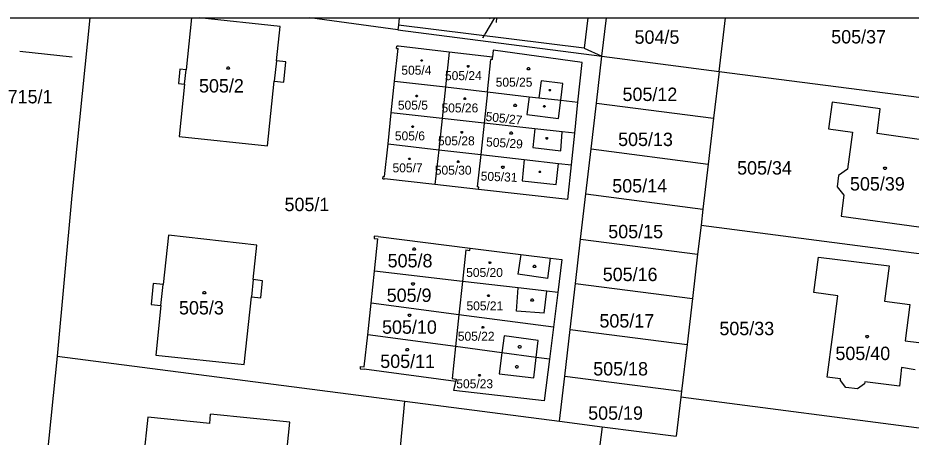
# Model space of a CAD drawing. Extents: x -639590 to -639298, y -1193269 to -1192863.
# Drawn here: x -639509.2 to -639395.8, y -1192916.5 to -1192863.3 of the extents above; entities that cross this region are included whole.
import ezdxf

# ---------------------------------------------------------------- set-up
doc = ezdxf.new("R2010")
doc.units = 0
for name, color, linetype in [('Vrstva 1', 7, 'Continuous'), ('Vrstva 2', 7, 'Continuous'), ('Vrstva 25', 7, 'Continuous'), ('Vrstva 4', 7, 'Continuous'), ('Vrstva 5', 7, 'Continuous'), ('Vrstva 61', 7, 'Continuous'), ('Vrstva 7', 7, 'Continuous')]:
    doc.layers.add(name, color=color, linetype=linetype)

msp = doc.modelspace()

# ---------------------------------------------------------------- linework, layer by layer
at = {"layer": 'Vrstva 1'}
for p, q in [((-639500.02, -1192863.27), (-639502.3, -1192885.82)), ((-639487.11, -1192863.27), (-639487.81, -1192869.85)), ((-639475.88, -1192864.37), (-639486.16, -1192863.27)), ((-639460.93, -1192864.78), (-639472.08, -1192863.27)), ((-639460.75, -1192863.27), (-639460.84, -1192864.19)), ((-639436.82, -1192863.27), (-639437.25, -1192867.1)), ((-639435.01, -1192868.14), (-639434.44, -1192863.27)), ((-639420.13, -1192870.07), (-639419.34, -1192863.27)), ((-639476.34, -1192868.73), (-639475.88, -1192864.37)), ((-639460.84, -1192864.19), (-639460.93, -1192864.78)), ((-639460.93, -1192864.78), (-639435.01, -1192868.14)), ((-639437.25, -1192867.1), (-639460.84, -1192864.19)), ((-639461.33, -1192871.31), (-639460.89, -1192867.17)), ((-639461.09, -1192867.15), (-639461.06, -1192866.85)), ((-639461.09, -1192867.15), (-639460.89, -1192867.17)), ((-639460.86, -1192866.87), (-639461.06, -1192866.85)), ((-639454.41, -1192867.62), (-639460.86, -1192866.87)), ((-639437.25, -1192867.1), (-639435.01, -1192868.14)), ((-639454.41, -1192867.62), (-639454.88, -1192872.05)), ((-639448.89, -1192868.27), (-639454.41, -1192867.62)), ((-639448.92, -1192868.57), (-639448.89, -1192868.27)), ((-639448.83, -1192867.36), (-639448.89, -1192868.27)), ((-639437.53, -1192868.96), (-639448.83, -1192867.36)), ((-639435.71, -1192874.11), (-639435.01, -1192868.14)), ((-639435.01, -1192868.14), (-639420.13, -1192870.07)), ((-639475.15, -1192868.85), (-639476.34, -1192868.73)), ((-639475.42, -1192871.43), (-639475.15, -1192868.85)), ((-639449.55, -1192872.67), (-639449.12, -1192868.55)), ((-639448.92, -1192868.57), (-639449.12, -1192868.55)), ((-639438.06, -1192873.99), (-639437.53, -1192868.96)), ((-639488.6, -1192869.77), (-639488.79, -1192871.6)), ((-639487.81, -1192869.85), (-639488.6, -1192869.77)), ((-639420.13, -1192870.07), (-639420.83, -1192876.03)), ((-639420.13, -1192870.07), (-639385.35, -1192874.56)), ((-639488.79, -1192871.6), (-639488, -1192871.69)), ((-639488, -1192871.69), (-639488.7, -1192878.32)), ((-639477.47, -1192879.53), (-639476.61, -1192871.31)), ((-639476.61, -1192871.31), (-639475.42, -1192871.43)), ((-639461.76, -1192875.34), (-639461.33, -1192871.31)), ((-639461.33, -1192871.31), (-639454.88, -1192872.05)), ((-639454.88, -1192872.05), (-639455.31, -1192876.05)), ((-639454.88, -1192872.05), (-639449.55, -1192872.67)), ((-639449.55, -1192872.67), (-639449.96, -1192876.65)), ((-639449.55, -1192872.67), (-639444.26, -1192873.28)), ((-639444.26, -1192873.28), (-639443.02, -1192873.42)), ((-639443.02, -1192873.42), (-639440.23, -1192873.74)), ((-639440.23, -1192873.74), (-639438.06, -1192873.99)), ((-639438.47, -1192877.92), (-639438.06, -1192873.99)), ((-639405.77, -1192873.99), (-639406.23, -1192877.35)), ((-639399.68, -1192874.84), (-639405.77, -1192873.99)), ((-639436.38, -1192879.92), (-639435.71, -1192874.11)), ((-639435.71, -1192874.11), (-639420.83, -1192876.03)), ((-639400.07, -1192877.95), (-639399.68, -1192874.84)), ((-639462.17, -1192879.28), (-639461.76, -1192875.34)), ((-639455.31, -1192876.05), (-639461.76, -1192875.34)), ((-639455.31, -1192876.05), (-639455.73, -1192880.02)), ((-639449.96, -1192876.65), (-639455.31, -1192876.05)), ((-639420.83, -1192876.03), (-639421.51, -1192881.84)), ((-639449.96, -1192876.65), (-639450.4, -1192880.62)), ((-639443.55, -1192877.36), (-639449.96, -1192876.65)), ((-639440.06, -1192877.74), (-639443.55, -1192877.36)), ((-639406.23, -1192877.35), (-639403.2, -1192877.77)), ((-639488.7, -1192878.32), (-639477.47, -1192879.53)), ((-639438.47, -1192877.92), (-639440.06, -1192877.74)), ((-639438.89, -1192881.94), (-639438.47, -1192877.92)), ((-639403.2, -1192877.77), (-639403.85, -1192882.5)), ((-639393.25, -1192878.92), (-639400.07, -1192877.95)), ((-639462.61, -1192883.42), (-639462.17, -1192879.28)), ((-639462.17, -1192879.28), (-639455.73, -1192880.02)), ((-639455.73, -1192880.02), (-639456.21, -1192884.44)), ((-639455.73, -1192880.02), (-639450.4, -1192880.62)), ((-639450.4, -1192880.62), (-639450.84, -1192884.74)), ((-639450.4, -1192880.62), (-639444.87, -1192881.26)), ((-639437.05, -1192885.64), (-639436.38, -1192879.92)), ((-639436.38, -1192879.92), (-639421.51, -1192881.84)), ((-639444.87, -1192881.26), (-639440.52, -1192881.75)), ((-639440.52, -1192881.75), (-639438.89, -1192881.94)), ((-639439.35, -1192886.33), (-639438.89, -1192881.94)), ((-639421.51, -1192881.84), (-639422.19, -1192887.56)), ((-639403.85, -1192882.5), (-639404.96, -1192883.3)), ((-639462.84, -1192883.7), (-639462.81, -1192883.4)), ((-639462.84, -1192883.7), (-639462.64, -1192883.72)), ((-639462.81, -1192883.4), (-639462.61, -1192883.42)), ((-639456.21, -1192884.44), (-639462.64, -1192883.72)), ((-639404.96, -1192883.3), (-639405.16, -1192884.72)), ((-639450.67, -1192885.06), (-639456.21, -1192884.44)), ((-639450.64, -1192884.76), (-639450.84, -1192884.74)), ((-639450.67, -1192885.06), (-639450.64, -1192884.76)), ((-639439.35, -1192886.33), (-639450.67, -1192885.06)), ((-639405.16, -1192884.72), (-639404.3, -1192885.8)), ((-639502.3, -1192885.82), (-639504.16, -1192906.23)), ((-639437.72, -1192891.36), (-639437.05, -1192885.64)), ((-639437.05, -1192885.64), (-639422.19, -1192887.56)), ((-639404.3, -1192885.8), (-639404.66, -1192888.45)), ((-639422.19, -1192887.56), (-639422.43, -1192889.62)), ((-639404.66, -1192888.45), (-639394.77, -1192889.8)), ((-639422.43, -1192889.62), (-639422.86, -1192893.28)), ((-639422.43, -1192889.62), (-639388.91, -1192893.95)), ((-639490.05, -1192890.89), (-639490.72, -1192897.15)), ((-639478.82, -1192892.16), (-639490.05, -1192890.89)), ((-639463.92, -1192891), (-639463.95, -1192891.3)), ((-639463.42, -1192891.05), (-639463.92, -1192891)), ((-639463.42, -1192891.05), (-639451.76, -1192892.5)), ((-639479.29, -1192896.52), (-639478.82, -1192892.16)), ((-639463.95, -1192891.3), (-639463.45, -1192891.35)), ((-639463.89, -1192895.44), (-639463.45, -1192891.35)), ((-639438.37, -1192897), (-639437.72, -1192891.36)), ((-639437.72, -1192891.36), (-639422.86, -1192893.28)), ((-639452.3, -1192892.75), (-639452.72, -1192896.74)), ((-639452.3, -1192892.75), (-639451.8, -1192892.81)), ((-639451.8, -1192892.81), (-639451.76, -1192892.5)), ((-639451.76, -1192892.5), (-639445.33, -1192893.31)), ((-639445.33, -1192893.31), (-639441.55, -1192893.78)), ((-639422.86, -1192893.28), (-639423.52, -1192898.92)), ((-639441.55, -1192893.78), (-639440.09, -1192893.96)), ((-639440.09, -1192893.96), (-639440.62, -1192898.15)), ((-639408.11, -1192898.17), (-639407.53, -1192893.65)), ((-639407.53, -1192893.65), (-639398.54, -1192894.78)), ((-639464.33, -1192899.52), (-639463.89, -1192895.44)), ((-639452.72, -1192896.74), (-639463.89, -1192895.44)), ((-639398.54, -1192894.78), (-639399.12, -1192899.27)), ((-639478.1, -1192896.65), (-639479.29, -1192896.52)), ((-639478.33, -1192898.83), (-639478.1, -1192896.65)), ((-639452.72, -1192896.74), (-639453.17, -1192900.97)), ((-639445.63, -1192897.57), (-639452.72, -1192896.74)), ((-639491.97, -1192897.02), (-639492.25, -1192899.67)), ((-639490.72, -1192897.15), (-639491.97, -1192897.02)), ((-639442, -1192897.99), (-639445.63, -1192897.57)), ((-639439.05, -1192902.85), (-639438.37, -1192897)), ((-639438.37, -1192897), (-639423.52, -1192898.92)), ((-639480.44, -1192907.28), (-639479.52, -1192898.7)), ((-639479.52, -1192898.7), (-639478.33, -1192898.83)), ((-639440.62, -1192898.15), (-639442, -1192897.99)), ((-639440.62, -1192898.15), (-639441.17, -1192902.54)), ((-639423.52, -1192898.92), (-639424.21, -1192904.77)), ((-639405.08, -1192898.56), (-639408.11, -1192898.17)), ((-639405.71, -1192903.49), (-639405.08, -1192898.56)), ((-639492.25, -1192899.67), (-639491, -1192899.81)), ((-639491, -1192899.81), (-639491.67, -1192906.12)), ((-639464.75, -1192903.51), (-639464.33, -1192899.52)), ((-639453.17, -1192900.97), (-639464.33, -1192899.52)), ((-639399.12, -1192899.27), (-639395.93, -1192899.67)), ((-639395.93, -1192899.67), (-639396.51, -1192904.3)), ((-639453.17, -1192900.97), (-639453.6, -1192905.02)), ((-639441.17, -1192902.54), (-639453.17, -1192900.97)), ((-639465.19, -1192907.6), (-639464.75, -1192903.51)), ((-639453.6, -1192905.02), (-639464.75, -1192903.51)), ((-639441.17, -1192902.54), (-639441.69, -1192906.63)), ((-639439.74, -1192908.77), (-639439.05, -1192902.85)), ((-639439.05, -1192902.85), (-639424.21, -1192904.77)), ((-639406.4, -1192908.89), (-639405.71, -1192903.49)), ((-639396.51, -1192904.3), (-639394.77, -1192904.49)), ((-639453.6, -1192905.02), (-639454.04, -1192909.09)), ((-639447.72, -1192905.81), (-639453.6, -1192905.02)), ((-639443.36, -1192906.4), (-639447.72, -1192905.81)), ((-639424.21, -1192904.77), (-639424.9, -1192910.69)), ((-639504.16, -1192906.23), (-639505.82, -1192922.39)), ((-639504.16, -1192906.23), (-639460.05, -1192911.94)), ((-639491.67, -1192906.12), (-639480.44, -1192907.28)), ((-639441.69, -1192906.63), (-639443.36, -1192906.4)), ((-639441.69, -1192906.63), (-639442.36, -1192911.91)), ((-639465.69, -1192907.55), (-639465.72, -1192907.83)), ((-639465.72, -1192907.83), (-639465.22, -1192907.9)), ((-639465.69, -1192907.55), (-639465.19, -1192907.6)), ((-639453.58, -1192909.45), (-639465.22, -1192907.9)), ((-639397, -1192907.67), (-639397.25, -1192910.06)), ((-639395.23, -1192907.97), (-639397, -1192907.67)), ((-639454.04, -1192909.09), (-639453.54, -1192909.15)), ((-639453.54, -1192909.15), (-639453.58, -1192909.45)), ((-639440.41, -1192914.49), (-639439.74, -1192908.77)), ((-639439.74, -1192908.77), (-639424.9, -1192910.69)), ((-639404.71, -1192909.1), (-639406.4, -1192908.89)), ((-639404.74, -1192909.33), (-639404.71, -1192909.1)), ((-639453.83, -1192910.59), (-639453.58, -1192909.45)), ((-639404.04, -1192910.2), (-639404.74, -1192909.33)), ((-639402.55, -1192910.39), (-639404.04, -1192910.2)), ((-639401.66, -1192909.73), (-639402.55, -1192910.39)), ((-639401.63, -1192909.5), (-639401.66, -1192909.73)), ((-639397.25, -1192910.06), (-639401.63, -1192909.5)), ((-639442.36, -1192911.91), (-639453.83, -1192910.59)), ((-639424.99, -1192911.45), (-639425.57, -1192916.41)), ((-639424.9, -1192910.69), (-639424.99, -1192911.45)), ((-639391.47, -1192915.8), (-639424.99, -1192911.45)), ((-639461.52, -1192927.91), (-639460.05, -1192911.94)), ((-639460.05, -1192911.94), (-639440.41, -1192914.49)), ((-639484.79, -1192914.79), (-639484.7, -1192913.59)), ((-639474.65, -1192914.63), (-639484.7, -1192913.59)), ((-639492.68, -1192913.98), (-639493.6, -1192922.99)), ((-639484.79, -1192914.79), (-639492.68, -1192913.98)), ((-639475.12, -1192919.21), (-639474.65, -1192914.63)), ((-639440.41, -1192914.49), (-639434.99, -1192915.19)), ((-639434.99, -1192915.19), (-639437.01, -1192931.02)), ((-639434.99, -1192915.19), (-639425.57, -1192916.41))]:
    msp.add_line(p, q, dxfattribs=at)
at = {"layer": 'Vrstva 25'}
msp.add_line((-639508.9, -1192867.52), (-639502.29, -1192868.24), dxfattribs=at)
at = {"layer": 'Vrstva 4'}
for p, q in [((-639476.34, -1192868.73), (-639476.61, -1192871.31)), ((-639488, -1192871.69), (-639487.81, -1192869.85)), ((-639442.74, -1192871.25), (-639443.02, -1192873.42)), ((-639439.96, -1192871.59), (-639442.74, -1192871.25)), ((-639440.23, -1192873.74), (-639439.96, -1192871.59)), ((-639444.26, -1192873.28), (-639444.55, -1192875.56)), ((-639440.51, -1192876.06), (-639440.23, -1192873.74)), ((-639444.55, -1192875.56), (-639440.51, -1192876.06)), ((-639443.55, -1192877.36), (-639443.8, -1192879.75)), ((-639440.25, -1192880.15), (-639440.06, -1192877.74)), ((-639443.8, -1192879.75), (-639440.25, -1192880.15)), ((-639444.87, -1192881.26), (-639445.13, -1192883.97)), ((-639440.82, -1192884.44), (-639440.52, -1192881.75)), ((-639445.13, -1192883.97), (-639440.82, -1192884.44)), ((-639445.33, -1192893.31), (-639445.69, -1192895.83)), ((-639441.88, -1192896.38), (-639441.55, -1192893.78)), ((-639479.29, -1192896.52), (-639479.52, -1192898.7)), ((-639441.88, -1192896.38), (-639445.69, -1192895.83)), ((-639491, -1192899.81), (-639490.72, -1192897.15)), ((-639445.85, -1192900.51), (-639445.63, -1192897.57)), ((-639442.33, -1192900.78), (-639442, -1192897.99)), ((-639442.33, -1192900.78), (-639445.85, -1192900.51)), ((-639447.44, -1192903.64), (-639447.72, -1192905.81)), ((-639443.1, -1192904.23), (-639447.44, -1192903.64)), ((-639443.36, -1192906.4), (-639443.1, -1192904.23)), ((-639447.72, -1192905.81), (-639448.07, -1192908.49)), ((-639443.68, -1192909), (-639443.36, -1192906.4)), ((-639448.07, -1192908.49), (-639443.68, -1192909))]:
    msp.add_line(p, q, dxfattribs=at)
at = {"layer": 'Vrstva 5'}
for points in [[(-639482.38, -1192869.5), (-639482.29, -1192869.65), (-639482.38, -1192869.8), (-639482.56, -1192869.8), (-639482.65, -1192869.65), (-639482.56, -1192869.5)], [(-639457.84, -1192868.58), (-639457.78, -1192868.68), (-639457.84, -1192868.78), (-639457.96, -1192868.78), (-639458.02, -1192868.68), (-639457.96, -1192868.58)], [(-639451.94, -1192869.34), (-639451.88, -1192869.44), (-639451.94, -1192869.54), (-639452.06, -1192869.54), (-639452.12, -1192869.44), (-639452.06, -1192869.34)], [(-639444.24, -1192869.59), (-639444.15, -1192869.74), (-639444.24, -1192869.89), (-639444.42, -1192869.89), (-639444.51, -1192869.74), (-639444.42, -1192869.59)], [(-639441.57, -1192872.35), (-639441.51, -1192872.45), (-639441.57, -1192872.55), (-639441.69, -1192872.55), (-639441.75, -1192872.45), (-639441.69, -1192872.35)], [(-639458.48, -1192873.08), (-639458.42, -1192873.18), (-639458.48, -1192873.28), (-639458.6, -1192873.28), (-639458.66, -1192873.18), (-639458.6, -1192873.08)], [(-639452.36, -1192873.43), (-639452.3, -1192873.53), (-639452.36, -1192873.63), (-639452.48, -1192873.63), (-639452.54, -1192873.53), (-639452.48, -1192873.43)], [(-639445.93, -1192874.23), (-639445.84, -1192874.38), (-639445.93, -1192874.53), (-639446.11, -1192874.53), (-639446.2, -1192874.38), (-639446.11, -1192874.23)], [(-639442.27, -1192874.41), (-639442.21, -1192874.51), (-639442.27, -1192874.61), (-639442.39, -1192874.61), (-639442.45, -1192874.51), (-639442.39, -1192874.41)], [(-639458.99, -1192876.99), (-639458.93, -1192877.09), (-639458.99, -1192877.19), (-639459.11, -1192877.19), (-639459.17, -1192877.09), (-639459.11, -1192876.99)], [(-639452.74, -1192877.71), (-639452.68, -1192877.81), (-639452.74, -1192877.91), (-639452.86, -1192877.91), (-639452.92, -1192877.81), (-639452.86, -1192877.71)], [(-639446.45, -1192877.76), (-639446.36, -1192877.91), (-639446.45, -1192878.06), (-639446.63, -1192878.06), (-639446.72, -1192877.91), (-639446.63, -1192877.76)], [(-639441.95, -1192878.48), (-639441.89, -1192878.58), (-639441.95, -1192878.68), (-639442.07, -1192878.68), (-639442.13, -1192878.58), (-639442.07, -1192878.48)], [(-639459.4, -1192881.08), (-639459.34, -1192881.18), (-639459.4, -1192881.28), (-639459.52, -1192881.28), (-639459.58, -1192881.18), (-639459.52, -1192881.08)], [(-639453.21, -1192881.43), (-639453.15, -1192881.53), (-639453.21, -1192881.63), (-639453.33, -1192881.63), (-639453.39, -1192881.53), (-639453.33, -1192881.43)], [(-639447.5, -1192882.09), (-639447.41, -1192882.24), (-639447.5, -1192882.39), (-639447.68, -1192882.39), (-639447.77, -1192882.24), (-639447.68, -1192882.09)], [(-639442.84, -1192882.73), (-639442.78, -1192882.83), (-639442.84, -1192882.93), (-639442.96, -1192882.93), (-639443.02, -1192882.83), (-639442.96, -1192882.73)], [(-639398.99, -1192882.23), (-639398.9, -1192882.38), (-639398.99, -1192882.53), (-639399.17, -1192882.53), (-639399.26, -1192882.38), (-639399.17, -1192882.23)], [(-639458.76, -1192892.48), (-639458.67, -1192892.63), (-639458.76, -1192892.78), (-639458.94, -1192892.78), (-639459.03, -1192892.63), (-639458.94, -1192892.48)], [(-639449.18, -1192894.27), (-639449.12, -1192894.37), (-639449.18, -1192894.47), (-639449.3, -1192894.47), (-639449.36, -1192894.37), (-639449.3, -1192894.27)], [(-639443.49, -1192894.68), (-639443.4, -1192894.83), (-639443.49, -1192894.98), (-639443.67, -1192894.98), (-639443.76, -1192894.83), (-639443.67, -1192894.68)], [(-639458.91, -1192896.92), (-639458.82, -1192897.07), (-639458.91, -1192897.22), (-639459.09, -1192897.22), (-639459.18, -1192897.07), (-639459.09, -1192896.92)], [(-639485.41, -1192898.04), (-639485.32, -1192898.19), (-639485.41, -1192898.34), (-639485.59, -1192898.34), (-639485.68, -1192898.19), (-639485.59, -1192898.04)], [(-639449.36, -1192898.44), (-639449.3, -1192898.54), (-639449.36, -1192898.64), (-639449.48, -1192898.64), (-639449.54, -1192898.54), (-639449.48, -1192898.44)], [(-639443.79, -1192898.97), (-639443.7, -1192899.12), (-639443.79, -1192899.27), (-639443.97, -1192899.27), (-639444.06, -1192899.12), (-639443.97, -1192898.97)], [(-639459.36, -1192900.89), (-639459.27, -1192901.04), (-639459.36, -1192901.19), (-639459.54, -1192901.19), (-639459.63, -1192901.04), (-639459.54, -1192900.89)], [(-639450.07, -1192902.47), (-639450.01, -1192902.57), (-639450.07, -1192902.67), (-639450.19, -1192902.67), (-639450.25, -1192902.57), (-639450.19, -1192902.47)], [(-639401.25, -1192903.6), (-639401.16, -1192903.75), (-639401.25, -1192903.9), (-639401.43, -1192903.9), (-639401.52, -1192903.75), (-639401.43, -1192903.6)], [(-639459.64, -1192905.27), (-639459.55, -1192905.42), (-639459.64, -1192905.57), (-639459.82, -1192905.57), (-639459.91, -1192905.42), (-639459.82, -1192905.27)], [(-639445.37, -1192904.9), (-639445.28, -1192905.05), (-639445.37, -1192905.2), (-639445.55, -1192905.2), (-639445.64, -1192905.05), (-639445.55, -1192904.9)], [(-639445.72, -1192907.44), (-639445.63, -1192907.59), (-639445.72, -1192907.74), (-639445.9, -1192907.74), (-639445.99, -1192907.59), (-639445.9, -1192907.44)], [(-639450.5, -1192908.58), (-639450.44, -1192908.68), (-639450.5, -1192908.78), (-639450.62, -1192908.78), (-639450.68, -1192908.68), (-639450.62, -1192908.58)]]:
    msp.add_lwpolyline(points, close=True, dxfattribs=at)
at = {"layer": 'Vrstva 61'}
msp.add_lwpolyline([(-639590.39, -1192863.27), (-639298.39, -1192863.27)], dxfattribs=at)
at = {"layer": 'Vrstva 7'}
for p in [(-639448.67, -1192863.27), (-639450.13, -1192865.8)]:
    msp.add_line(p, (-639449.87, -1192865.34), dxfattribs=at)
for points in [[(-639449.3, -1192863.36), (-639449.16, -1192863.27)], [(-639448.4, -1192863.27), (-639448.43, -1192863.86)]]:
    msp.add_lwpolyline(points, dxfattribs=at)

# ---------------------------------------------------------------- texts
at = {"layer": 'Vrstva 2'}
for s, height, p in [('504/5', 1.7, (-639430.87, -1192866.56)), ('505/37', 1.7, (-639405.9, -1192866.52)), ('504/8', 0.1, (-639450.34, -1192865.8)), ('505/4', 1.14, (-639460.48, -1192870.49)), ('505/24', 1.14, (-639454.94, -1192871.18)), ('505/2', 1.7, (-639486.17, -1192872.75)), ('505/25', 1.14, (-639448.5, -1192872.01)), ('715/1', 1.7, (-639510.46, -1192874.13)), ('505/12', 1.7, (-639432.4, -1192873.83)), ('505/5', 1.14, (-639460.92, -1192874.93)), ('505/26', 1.14, (-639455.38, -1192875.28)), ('505/6', 1.14, (-639461.3, -1192878.83)), ('505/28', 1.14, (-639455.83, -1192879.46)), ('505/13', 1.7, (-639432.96, -1192879.55)), ('505/7', 1.14, (-639461.6, -1192882.89)), ('505/30', 1.14, (-639456.23, -1192883.19)), ('505/34', 1.7, (-639417.85, -1192883.17)), ('505/14', 1.7, (-639433.7, -1192885.45)), ('505/39', 1.7, (-639403.52, -1192885.2)), ('505/1', 1.7, (-639475.31, -1192887.82)), ('505/15', 1.7, (-639434.21, -1192891.26)), ('505/8', 1.7, (-639462.22, -1192894.96)), ('505/20', 1.14, (-639452.25, -1192896.18)), ('505/16', 1.7, (-639434.91, -1192896.7)), ('505/9', 1.7, (-639462.34, -1192899.35)), ('505/3', 1.7, (-639488.71, -1192900.94)), ('505/21', 1.14, (-639452.21, -1192900.42)), ('505/17', 1.7, (-639435.33, -1192902.6)), ('505/10', 1.7, (-639462.93, -1192903.39)), ('505/33', 1.7, (-639420.1, -1192903.57)), ('505/22', 1.14, (-639453.31, -1192904.28)), ('505/40', 1.7, (-639405.37, -1192906.73)), ('505/11', 1.7, (-639463.16, -1192907.74)), ('505/18', 1.7, (-639436.12, -1192908.69)), ('505/23', 1.14, (-639453.5, -1192910.31)), ('505/19', 1.7, (-639436.76, -1192914.31))]:
    msp.add_text(s, height=height, dxfattribs=at).set_placement(p)
for s, rotation, p in [('505/27', 353.6296, (-639449.83, -1192876.34)), ('505/29', 356.3225, (-639449.75, -1192879.58)), ('505/31', 357.8121, (-639450.42, -1192883.93))]:
    msp.add_text(s, height=1.14, rotation=rotation, dxfattribs=at).set_placement(p)

doc.saveas('drawing.dxf')
